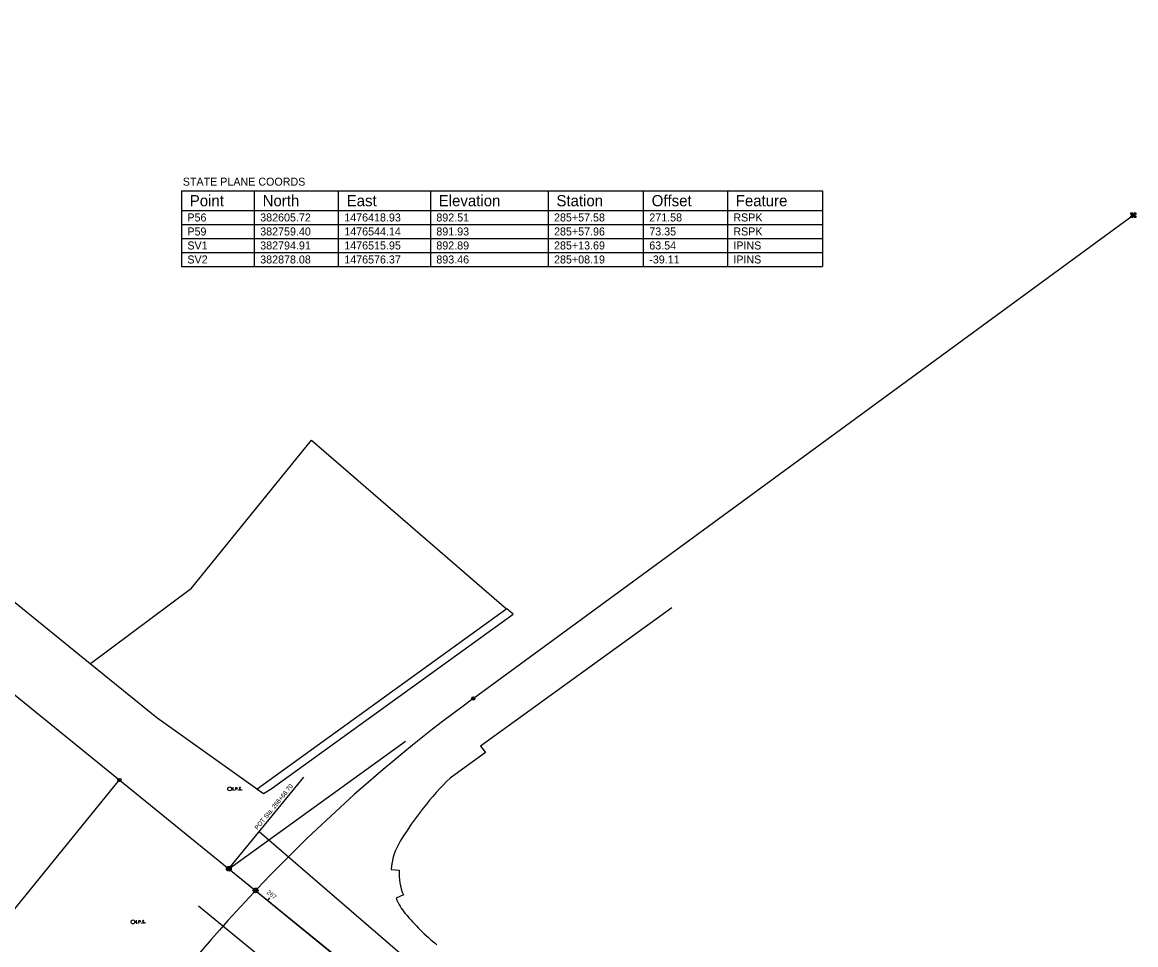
# Model space of a CAD drawing. Extents: x 1474076 to 1484331, y 375914 to 383395.
# Drawn here: x 1476447 to 1477142, y 382781 to 383357 of the extents above; entities that cross this region are included whole.
import ezdxf

# ---------------------------------------------------------------- set-up
doc = ezdxf.new("R2010")
doc.units = 0
for name, color, linetype in [('DV_X_Lot_Line', 7, 'Continuous'), ('DV_X_Property_Line', 7, 'Continuous'), ('RW_P_Esmt_TMP', 7, 'Continuous'), ('RW_X_Esmt_U', 7, 'Continuous'), ('SV_Control_Point', 7, 'Continuous'), ('SV_P_Control_Cells_Set', 7, 'Continuous'), ('SV_P_Mon_Cells_Set', 7, 'Continuous'), ('SV_X_Control_Cells_Found', 7, 'Continuous')]:
    doc.layers.add(name, color=color, linetype=linetype)

msp = doc.modelspace()

# ---------------------------------------------------------------- linework, layer by layer
at = {"layer": 'DV_X_Lot_Line'}
msp.add_lwpolyline([(1476489.36, 382956.28), (1476552.48, 383003.4), (1476627.56, 383095.93), (1476749.26, 382990.49)], dxfattribs=at)
at = {"layer": 'DV_X_Property_Line'}
for p, q in [((1476387.66, 383038.82), (1476489.27, 382956.35)), ((1476749.44, 382990.62), (1476593.51, 382877.9)), ((1476602.18, 382878.08), (1476753.33, 382987.24)), ((1476602.18, 382878.08), (1476753.33, 382987.24)), ((1476852.58, 382991.14), (1476733.09, 382904.76)), ((1476753.33, 382987.24), (1476749.44, 382990.62)), ((1476489.27, 382956.35), (1476530.81, 382922.63)), ((1476530.81, 382922.63), (1476597.4, 382875.13)), ((1476733.09, 382904.76), (1476736.05, 382900.73)), ((1476736.05, 382900.73), (1476724.01, 382892.03)), ((1476724.01, 382892.03), (1476713.99, 382884.8)), ((1476593.51, 382877.9), (1476597.4, 382875.13)), ((1476597.4, 382875.13), (1476602.18, 382878.08)), ((1476597.4, 382875.13), (1476602.18, 382878.08)), ((1476677.23, 382827.56), (1476682.21, 382827.24)), ((1476684.83, 382811.73), (1476680.28, 382809.72))]:
    msp.add_line(p, q, dxfattribs=at)
for centre, radius, start, end in [((1476865.27, 382733.44), 214, 134.98461, 148.44264), ((1476716.14, 382825.01), 39, 148.42609, 176.25661), ((1476716.14, 382824.99), 34, 176.20988, 202.95817), ((1476716.18, 382824.95), 39, 202.98183, 219.39144), ((1476793.3, 382888.61), 139, 219.49938, 230.96839)]:
    msp.add_arc(centre, radius, start, end, dxfattribs=at)
at = {"layer": 'RW_P_Esmt_TMP'}
for p, q in [((1475924.2, 383357.02), (1476575.86, 382828.12)), ((1476728.51, 382934.52), (1477140.75, 383236.47)), ((1476575.86, 382828.11), (1476686.25, 382907.92)), ((1476336.36, 382672.73), (1476507.5, 382883.6)), ((1476576.49, 382828.89), (1476622.61, 382885.38)), ((1476576.49, 382828.89), (1476622.67, 382885.33)), ((1476575.86, 382828.12), (1477045.83, 382446.68)), ((1476575.86, 382828.12), (1477032.12, 382455.61)), ((1476600.11, 382808.32), (1476601.37, 382809.87))]:
    msp.add_line(p, q, dxfattribs=at)
for centre in [(1477140.75, 383236.47), (1476728.51, 382934.52), (1476507.5, 382883.6), (1476575.86, 382828.12), (1476575.86, 382828.12), (1476575.86, 382828.12)]:
    msp.add_circle(centre, 1, dxfattribs=at)
msp.add_arc((1477319.42, 382127.78), 1000, 126.22135, 140.82833, dxfattribs=at)
at = {"layer": 'RW_X_Esmt_U'}
for p, q in [((1476594.86, 382851.34), (1477041.22, 382466.74)), ((1476556.86, 382804.9), (1477012.72, 382431.91))]:
    msp.add_line(p, q, dxfattribs=at)
at = {"layer": 'SV_P_Control_Cells_Set'}
msp.add_line((1477140.75, 383236.47), (1477140.75, 383236.47), dxfattribs=at)
msp.add_line((1477140.75, 383236.47), (1477140.75, 383236.47), dxfattribs=at)
for points in [[(1477139.25, 383236.85), (1477139.25, 383237.97), (1477140.37, 383237.97)], [(1477139.25, 383236.85), (1477139.25, 383237.97), (1477140.37, 383237.97)], [(1477141.1, 383237.97), (1477142.25, 383237.97), (1477142.25, 383236.85)], [(1477141.11, 383237.97), (1477142.25, 383237.97), (1477142.25, 383236.85)], [(1477140.37, 383234.97), (1477139.25, 383234.97), (1477139.25, 383236.09)], [(1477140.37, 383234.97), (1477139.25, 383234.97), (1477139.25, 383236.09)], [(1477140.01, 383235.47), (1477140.01, 383237.47), (1477140.75, 383235.47), (1477141.49, 383237.47), (1477141.49, 383235.47)], [(1477140.01, 383235.47), (1477140.01, 383237.47), (1477140.75, 383235.47), (1477141.49, 383237.47), (1477141.49, 383235.47)], [(1477142.25, 383236.09), (1477142.25, 383234.97), (1477141.1, 383234.97)], [(1477142.25, 383236.09), (1477142.25, 383234.97), (1477141.11, 383234.97)]]:
    msp.add_lwpolyline(points, dxfattribs=at)
for centre, radius in [((1476575.86, 382828.12), 1.5), ((1476575.86, 382828.12), 1.5), ((1476575.86, 382828.12), 0.8), ((1476575.86, 382828.12), 0.8), ((1476592.56, 382814.56), 1.5), ((1476592.56, 382814.56), 1.5), ((1476592.56, 382814.56), 0.8), ((1476592.56, 382814.56), 0.8)]:
    msp.add_circle(centre, radius, dxfattribs=at)
at = {"layer": 'SV_P_Mon_Cells_Set'}
for points in [[(1476578.39, 382878.88), (1476578.74, 382878.88)], [(1476578.39, 382877.28), (1476578.74, 382877.28)], [(1476578.56, 382877.28), (1476578.56, 382878.88)], [(1476579.52, 382877.49), (1476579.58, 382877.49), (1476579.61, 382877.47), (1476579.64, 382877.42), (1476579.64, 382877.36), (1476579.61, 382877.3), (1476579.58, 382877.28), (1476579.52, 382877.28), (1476579.49, 382877.3), (1476579.46, 382877.36), (1476579.46, 382877.42), (1476579.49, 382877.47), (1476579.52, 382877.49)], [(1476580.13, 382877.28), (1476580.13, 382878.88), (1476580.66, 382878.88), (1476580.71, 382878.87), (1476580.79, 382878.84), (1476580.82, 382878.82), (1476580.86, 382878.79), (1476580.9, 382878.73), (1476580.93, 382878.67), (1476580.96, 382878.56), (1476580.96, 382878.41), (1476580.94, 382878.36), (1476580.92, 382878.29), (1476580.88, 382878.2), (1476580.83, 382878.16), (1476580.8, 382878.14), (1476580.75, 382878.11), (1476580.66, 382878.1), (1476580.13, 382878.1)], [(1476581.77, 382877.49), (1476581.83, 382877.49), (1476581.86, 382877.47), (1476581.89, 382877.42), (1476581.89, 382877.36), (1476581.86, 382877.3), (1476581.83, 382877.28), (1476581.77, 382877.28), (1476581.74, 382877.3), (1476581.7, 382877.36), (1476581.7, 382877.42), (1476581.74, 382877.47), (1476581.77, 382877.49)], [(1476583.14, 382878.77), (1476583.12, 382878.79), (1476583.08, 382878.82), (1476582.98, 382878.85), (1476582.86, 382878.88), (1476582.77, 382878.88), (1476582.74, 382878.88), (1476582.6, 382878.84), (1476582.48, 382878.77), (1476582.4, 382878.67), (1476582.38, 382878.56), (1476582.38, 382878.49), (1476582.4, 382878.39), (1476582.49, 382878.3), (1476583.09, 382877.92), (1476583.15, 382877.87), (1476583.17, 382877.82), (1476583.19, 382877.75), (1476583.19, 382877.67), (1476583.18, 382877.59), (1476583.17, 382877.54), (1476583.15, 382877.48), (1476583.13, 382877.43), (1476583.1, 382877.39), (1476583.07, 382877.36), (1476583.04, 382877.33), (1476582.99, 382877.3), (1476582.96, 382877.29), (1476582.86, 382877.28), (1476582.71, 382877.28), (1476582.61, 382877.3), (1476582.47, 382877.39), (1476582.38, 382877.47)], [(1476583.95, 382877.49), (1476584.01, 382877.49), (1476584.04, 382877.47), (1476584.07, 382877.42), (1476584.07, 382877.36), (1476584.04, 382877.3), (1476584.01, 382877.28), (1476583.95, 382877.28), (1476583.92, 382877.3), (1476583.89, 382877.36), (1476583.89, 382877.42), (1476583.92, 382877.47), (1476583.95, 382877.49)], [(1476517.96, 382795.71), (1476518.32, 382795.71)], [(1476517.96, 382794.11), (1476518.32, 382794.11)], [(1476518.14, 382794.11), (1476518.14, 382795.71)], [(1476519.1, 382794.32), (1476519.16, 382794.32), (1476519.19, 382794.3), (1476519.22, 382794.25), (1476519.22, 382794.19), (1476519.19, 382794.14), (1476519.16, 382794.11), (1476519.1, 382794.11), (1476519.07, 382794.14), (1476519.03, 382794.19), (1476519.03, 382794.25), (1476519.07, 382794.3), (1476519.1, 382794.32)], [(1476519.71, 382794.11), (1476519.71, 382795.71), (1476520.24, 382795.71), (1476520.29, 382795.7), (1476520.37, 382795.67), (1476520.4, 382795.65), (1476520.43, 382795.62), (1476520.48, 382795.56), (1476520.51, 382795.5), (1476520.53, 382795.4), (1476520.53, 382795.24), (1476520.52, 382795.19), (1476520.5, 382795.12), (1476520.46, 382795.03), (1476520.41, 382794.99), (1476520.38, 382794.97), (1476520.32, 382794.94), (1476520.24, 382794.93), (1476519.71, 382794.93)], [(1476521.35, 382794.32), (1476521.4, 382794.32), (1476521.44, 382794.3), (1476521.47, 382794.25), (1476521.47, 382794.19), (1476521.44, 382794.14), (1476521.4, 382794.11), (1476521.35, 382794.11), (1476521.32, 382794.14), (1476521.28, 382794.19), (1476521.28, 382794.25), (1476521.32, 382794.3), (1476521.35, 382794.32)], [(1476522.72, 382795.6), (1476522.69, 382795.62), (1476522.66, 382795.65), (1476522.56, 382795.69), (1476522.44, 382795.71), (1476522.35, 382795.71), (1476522.32, 382795.71), (1476522.18, 382795.67), (1476522.05, 382795.6), (1476521.98, 382795.5), (1476521.96, 382795.4), (1476521.96, 382795.32), (1476521.98, 382795.22), (1476522.07, 382795.13), (1476522.67, 382794.75), (1476522.73, 382794.7), (1476522.75, 382794.65), (1476522.77, 382794.58), (1476522.77, 382794.5), (1476522.76, 382794.43), (1476522.75, 382794.38), (1476522.73, 382794.31), (1476522.7, 382794.26), (1476522.68, 382794.22), (1476522.65, 382794.19), (1476522.62, 382794.16), (1476522.57, 382794.14), (1476522.54, 382794.12), (1476522.44, 382794.11), (1476522.29, 382794.11), (1476522.19, 382794.14), (1476522.04, 382794.22), (1476521.96, 382794.3)], [(1476523.53, 382794.32), (1476523.59, 382794.32), (1476523.62, 382794.3), (1476523.65, 382794.25), (1476523.65, 382794.19), (1476523.62, 382794.14), (1476523.59, 382794.11), (1476523.53, 382794.11), (1476523.5, 382794.14), (1476523.47, 382794.19), (1476523.47, 382794.25), (1476523.5, 382794.3), (1476523.53, 382794.32)]]:
    msp.add_lwpolyline(points, dxfattribs=at)
for centre in [(1476576.37, 382878.08), (1476515.95, 382794.91)]:
    msp.add_circle(centre, 1.2, dxfattribs=at)
at = {"layer": 'SV_X_Control_Cells_Found'}
for p, q in [((1476546.19, 383251.67), (1476946.69, 383251.67)), ((1476546.19, 383251.67), (1476546.19, 383204.42)), ((1476591.69, 383251.67), (1476591.69, 383204.42)), ((1476644.19, 383251.67), (1476644.19, 383204.42)), ((1476701.69, 383251.67), (1476701.69, 383204.42)), ((1476775.19, 383251.67), (1476775.19, 383204.42)), ((1476834.69, 383251.67), (1476834.69, 383204.42)), ((1476887.19, 383251.67), (1476887.19, 383204.42)), ((1476946.69, 383251.67), (1476946.69, 383204.42)), ((1476946.69, 383251.67), (1476946.69, 383204.42)), ((1476546.19, 383239.42), (1476946.69, 383239.42)), ((1476546.19, 383230.67), (1476946.69, 383230.67)), ((1476546.19, 383230.67), (1476946.69, 383230.67)), ((1476546.19, 383230.67), (1476946.69, 383230.67)), ((1476546.19, 383230.67), (1476946.69, 383230.67)), ((1476546.19, 383230.67), (1476946.69, 383230.67)), ((1476546.19, 383230.67), (1476946.69, 383230.67)), ((1476546.19, 383230.67), (1476946.69, 383230.67)), ((1476546.19, 383221.92), (1476946.69, 383221.92)), ((1476546.19, 383221.92), (1476946.69, 383221.92)), ((1476546.19, 383221.92), (1476946.69, 383221.92)), ((1476546.19, 383221.92), (1476946.69, 383221.92)), ((1476546.19, 383221.92), (1476946.69, 383221.92)), ((1476546.19, 383221.92), (1476946.69, 383221.92)), ((1476546.19, 383221.92), (1476946.69, 383221.92)), ((1476546.19, 383213.17), (1476946.69, 383213.17)), ((1476546.19, 383213.17), (1476946.69, 383213.17)), ((1476546.19, 383213.17), (1476946.69, 383213.17)), ((1476546.19, 383213.17), (1476946.69, 383213.17)), ((1476546.19, 383213.17), (1476946.69, 383213.17)), ((1476546.19, 383213.17), (1476946.69, 383213.17)), ((1476546.19, 383213.17), (1476946.69, 383213.17)), ((1476546.19, 383204.42), (1476946.69, 383204.42)), ((1476546.19, 383204.42), (1476946.69, 383204.42)), ((1476546.19, 383204.42), (1476946.69, 383204.42)), ((1476546.19, 383204.42), (1476946.69, 383204.42)), ((1476546.19, 383204.42), (1476946.69, 383204.42)), ((1476546.19, 383204.42), (1476946.69, 383204.42)), ((1476546.19, 383204.42), (1476946.69, 383204.42))]:
    msp.add_line(p, q, dxfattribs=at)

# ---------------------------------------------------------------- texts
at = {"layer": 'RW_P_Esmt_TMP'}
for s, rotation, p in [('POT Sta. 266+68.70', 50.76971, (1476593.75, 382852.24)), ('POT Sta. 266+68.70', 50.70966, (1476593.77, 382852.22)), ('267', 320.76971, (1476599.24, 382812.9))]:
    msp.add_text(s, height=2.8, rotation=rotation, dxfattribs=at).set_placement(p)
at = {"layer": 'SV_Control_Point'}
msp.add_text('STATE PLANE COORDS', height=5, dxfattribs=at).set_placement((1476547.08, 383254.92))
at = {"layer": 'SV_X_Control_Cells_Found'}
for s, height, p in [('Point', 7, (1476551.44, 383242.05)), ('North', 7, (1476596.94, 383242.05)), ('East', 7, (1476649.44, 383242.05)), ('Elevation', 7, (1476706.94, 383242.05)), ('Station', 7, (1476780.44, 383242.05)), ('Offset', 7, (1476839.94, 383242.05)), ('Feature', 7, (1476892.44, 383242.05)), ('P56', 5, (1476549.94, 383232.55)), ('382605.72', 5, (1476595.44, 383232.55)), ('1476418.93', 5, (1476647.94, 383232.55)), ('892.51', 5, (1476705.44, 383232.55)), ('285+57.58', 5, (1476778.94, 383232.55)), ('271.58', 5, (1476838.44, 383232.55)), ('RSPK', 5, (1476890.94, 383232.55)), ('P59', 5, (1476549.94, 383223.8)), ('382759.40', 5, (1476595.44, 383223.8)), ('1476544.14', 5, (1476647.94, 383223.8)), ('891.93', 5, (1476705.44, 383223.8)), ('285+57.96', 5, (1476778.94, 383223.8)), ('73.35', 5, (1476838.44, 383223.8)), ('RSPK', 5, (1476890.94, 383223.8)), ('SV1', 5, (1476549.94, 383215.05)), ('382794.91', 5, (1476595.44, 383215.05)), ('1476515.95', 5, (1476647.94, 383215.05)), ('892.89', 5, (1476705.44, 383215.05)), ('285+13.69', 5, (1476778.94, 383215.05)), ('63.54', 5, (1476838.44, 383215.05)), ('IPINS', 5, (1476890.94, 383215.05)), ('SV2', 5, (1476549.94, 383206.3)), ('382878.08', 5, (1476595.44, 383206.3)), ('1476576.37', 5, (1476647.94, 383206.3)), ('893.46', 5, (1476705.44, 383206.3)), ('285+08.19', 5, (1476778.94, 383206.3)), ('-39.11', 5, (1476838.44, 383206.3)), ('IPINS', 5, (1476890.94, 383206.3))]:
    msp.add_text(s, height=height, dxfattribs=at).set_placement(p)

doc.saveas('drawing.dxf')
